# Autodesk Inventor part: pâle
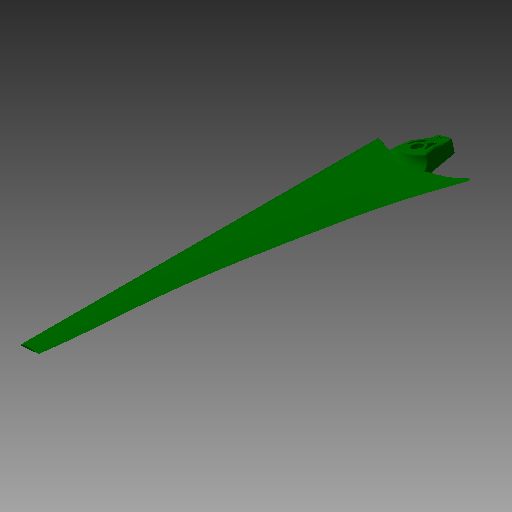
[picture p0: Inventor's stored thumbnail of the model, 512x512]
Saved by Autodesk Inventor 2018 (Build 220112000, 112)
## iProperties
Created: 2014-09
Part Number: pâle
Material: Générique
Document SubType Name: Modeling
Designer: papa
Density: 1 g/cm^3
Appearance: Par défaut
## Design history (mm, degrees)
node "pâle1"
node "pâle"
node "Base1"
